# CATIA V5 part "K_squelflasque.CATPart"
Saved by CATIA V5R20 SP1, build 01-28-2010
Part number: squelflasque
Publications: "longueurvbasflasque", "hauteurméplatflasque", "largeurméplatflasque"
Bounding box of the stored display mesh (mm): x -5 to 40.5, y -100 to 153.846, z 0 to 178
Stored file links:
  G:\Khaled_CFAO_2011\SIL\SIL_GR2\zthiebault\Khaled\CAD_ThinkMOTION\K_squelflasque.CATPart
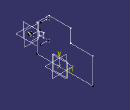
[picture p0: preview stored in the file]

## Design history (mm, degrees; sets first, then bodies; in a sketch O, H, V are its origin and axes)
Parameters
  longueurvbasflasque = 200 mm
  hauteurflasque = 178 mm
  `hauteurméplatflasque` = 60 mm
  `largeurméplatflasque` = 100 mm
DatumSurface1
Sketch1 on yz-plane, origin (0, 0, 0), H (0, 1, 0), V (0, 0, 1)
  point P1 (-100, 0)
  line L1 (53.8462, 178) -> (53.8462, 118)
  reference projected point E1 (-100, 0) from vertex of Line1
  line L2 (53.8462, 118) -> (153.8462, 118)
  line L3 (153.8462, 118) -> (153.8462, 0)
  point P5 (153.8462, 0)
  reference projected point E2 (153.8462, 0) from vertex of Line1
  point P6 (-52, 163)
  axis line L4 (-52, 163) -> (-52, 76)
  point P7 (-52, 76)
  point P8 (-52, 76)
  line L5 (53.8462, 178) -> (-46.1538, 178)
  line L6 (-46.1538, 178) -> (-100, 124.1538)
  line L7 (-100, 124.1538) -> (-100, 0)
  line L8 (-89, 98) -> (-69, 98)
  line L9 (-69, 98) -> (-69, 78)
  line L10 (-69, 78) -> (-89, 78)
  line L11 (-89, 78) -> (-89, 98)
  reference projected line E3 (-69, 78) -> (-69, 98) from edge of DatumCurve5
  reference projected line E4 (-69, 78) -> (-89, 78) from edge of DatumCurve6
  reference projected line E5 (-89, 98) -> (-89, 78) from edge of DatumCurve7
  reference projected line E6 (-89, 98) -> (-69, 98) from edge of DatumCurve8
  length L2 = 100 {= `largeurméplatflasque`}
  length L1 = 60 {= `hauteurméplatflasque`}
  distance P6 V = 52
  distance P6 P8 = 87
  distance P6 H = 163
  length L5 = 100
  angle H L6 = 45
  coincidence: P1 H, P1 E1, P5 H, P5 E2, P8 P7, L9 E3, L10 E4, L11 E5, L8 E6
  vertical: L1 V, L3 V, L4 V, L7 V, L9 V, L11 V
  horizontal: L2 H, L5 H, L8 H, L10 H
Set1 "setgéomflasque"
  Point1 "origine": (0, 0, 0)
  Line1: type Normal, RefPoint Point1, RefSkin zx-plane, Start -100 {= -longueurvbasflasque /2}, End 153.8462 {= longueurvbasflasque /1.3}
  DatumCurve1
  DatumSurface2
  DatumSurface3
  Point2: stored without definition
  Point3: stored without definition
  DatumPoint1
  Plane1: type OffsetPt, RefPlane yz-plane, RefPoint Sketch1.P6
  Plane2: type OffsetPt, RefPlane yz-plane, RefPoint Sketch1.P8
  Line2: type Normal, RefPoint Sketch1.P6, RefSkin Plane1, Start 30, End 0
  Line3: type Normal, RefPoint Sketch1.P8, RefSkin Plane2, Start 30, End 0
  Plane3: type OffsetPt, RefPlane Plane1, RefPoint vertex of Line2
  Plane4: type OffsetPt, RefPlane Plane2, RefPoint vertex of Line3
  DatumCurve2
  Line4: stored without definition
  DatumPoint2
  DatumCurve3
  Line5: stored without definition
  DatumCurve4
  Line6: type Normal, RefPoint Point1, RefSkin yz-plane, Start 0, End 5
  Plane5: type OffsetPt, RefPlane yz-plane, RefPoint vertex of Line6
  DatumCurve5 to DatumCurve8
  Line7: type Normal, RefPoint vertex [element of Sketch1 | element of Sketch1], RefSkin DatumSurface4, Start 0, End 30
  DatumSurface4
  Point4: type OnCurve, Support Line7, Length 35.5, Direction DatumCurve9
  DatumCurve9
  Plane6: type OffsetPt, RefPlane DatumSurface5, RefPoint Point4
  DatumSurface5
  Line8: type Normal, RefPoint Point4, RefSkin Plane6, Start 0, End 9.012
  Point5: type OnCurve, Support Line8, Length 0
  DatumSurface6
  Point6: stored without definition
  Point7: type OnCurve, Support Line8, Length 8
  Plane7: type OffsetPt, RefPlane xy-plane, RefPoint Point7
  Point8: stored without definition
  Line9: type Normal, RefPoint Point7, RefSkin Plane7, Start -2, End 0
  Point9: type OnCurve, Support Line9, Length 0.203
  Plane8: type OffsetPt, RefPlane Plane9, RefPoint Point9
  Plane9: stored without definition
  Line10: type Normal, RefPoint Point9, RefSkin Plane8, Start -5, End 5
Body1 (main body)
Relations
  Line1.Start = -longueurvbasflasque /1.4 (deactivated)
